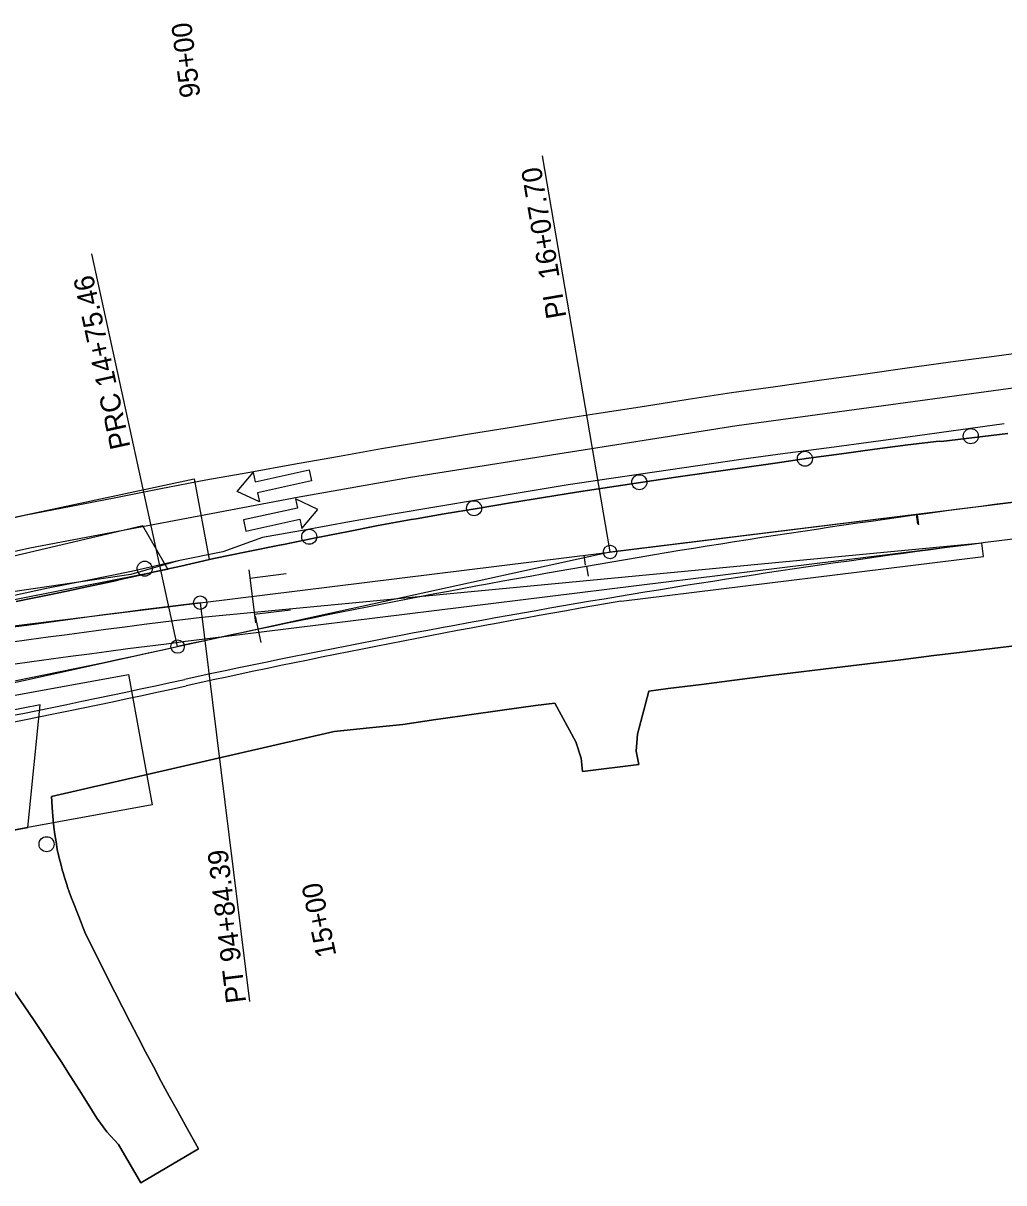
# Model space of a CAD drawing. Extents: x 1568809 to 1572786, y 728326 to 734907.
# Drawn here: x 1569721.8 to 1570014.8, y 731945.8 to 732292 of the extents above; entities that cross this region are included whole.
import ezdxf

# ---------------------------------------------------------------- set-up
doc = ezdxf.new("R2010")
doc.units = 0
for name, color, linetype in [('R_Horz Alg', 7, 'Continuous'), ('R_Horz Alg Annot', 7, 'Continuous'), ('R_MOT', 7, 'Continuous'), ('R_No Plot', 7, 'Continuous'), ('R_Proposed Const Limits_Fill', 7, 'Continuous'), ('R_Striping', 7, 'Continuous')]:
    doc.layers.add(name, color=color, linetype=linetype)

msp = doc.modelspace()

# ---------------------------------------------------------------- linework, layer by layer
at = {"layer": 'R_Horz Alg'}
msp.add_line((1569774.69, 732119.01), (1571082.41, 732280.73), dxfattribs=at)
for centre, radius, start, end in [((1570379.97, 729307.25), 2864.79, 97.05, 102.33591), ((1570243.51, 728328.17), 3819.72, 97.05, 102.61775), ((1569155.89, 734904.54), 2864.79, 276.60226, 282.33591)]:
    msp.add_arc(centre, radius, start, end, dxfattribs=at)
at = {"layer": 'R_Horz Alg Annot'}
for p, q in [((1569897.12, 732134.15), (1570028.36, 732150.38)), ((1569767.93, 732105.9), (1569897.12, 732134.15)), ((1569590.36, 732096.21), (1569774.69, 732119.01)), ((1569627.78, 732075.25), (1569767.93, 732105.9))]:
    msp.add_line(p, q, dxfattribs=at)
for points in [[(1569897.12, 732134.15), (1569876.92, 732252.44)], [(1569767.93, 732105.9), (1569742.3, 732223.13)], [(1569989.03, 732142.49), (1569988.67, 732145.47)], [(1569989.36, 732142.25), (1569988.95, 732145.23)], [(1569889.79, 732130.22), (1569889.42, 732133.2)], [(1569890.65, 732126.9), (1569890.14, 732129.85)], [(1569789.69, 732124.89), (1569790.67, 732116.95)], [(1569774.69, 732119.01), (1569789.42, 731999.91)], [(1569791.11, 732114.95), (1569792.75, 732107.12)]]:
    msp.add_lwpolyline(points, dxfattribs=at)
for centre in [(1569897.12, 732134.15), (1569774.69, 732119.01), (1569767.93, 732105.9)]:
    msp.add_circle(centre, 2, dxfattribs=at)
at = {"layer": 'R_MOT'}
for p, q in [((1569789.2, 732128.86), (1569791.16, 732112.98)), ((1569800.36, 732127.58), (1569789.52, 732126.24)), ((1569801.69, 732116.81), (1569790.85, 732115.47))]:
    msp.add_line(p, q, dxfattribs=at)
for points in [[(1569792.37, 732149.09), (1569785.71, 732152.25), (1569790.46, 732157.88), (1569791.06, 732155.14), (1569807.23, 732158.65), (1569807.95, 732155.35), (1569791.78, 732151.84)], [(1569805.05, 732141.18), (1569809.81, 732146.82), (1569803.14, 732149.97), (1569803.74, 732147.22), (1569787.57, 732143.71), (1569788.28, 732140.41), (1569804.46, 732143.93)]]:
    msp.add_lwpolyline(points, close=True, dxfattribs=at)
for centre in [(1570004.89, 732168.73), (1569955.34, 732161.99), (1569905.86, 732154.98), (1569856.5, 732147.21), (1569807.26, 732138.7), (1569758.1, 732129.16), (1569728.78, 732046.9)]:
    msp.add_circle(centre, 2.25, dxfattribs=at)
at = {"layer": 'R_No Plot'}
for p, q in [((1569599.2, 732118.84), (1569772.9, 732155.99)), ((1569772.9, 732155.99), (1569777.36, 732131.86)), ((1570008.21, 732136.8), (1569775.13, 732114.63)), ((1570008.21, 732136.8), (1569776.04, 732108.09)), ((1570008.7, 732132.83), (1570008.21, 732136.8)), ((1570008.7, 732132.83), (1570008.21, 732136.8)), ((1569900.4, 732119.44), (1570008.7, 732132.83)), ((1569900.4, 732119.44), (1570008.7, 732132.83)), ((1569814.7, 732080.55), (1569730.27, 732061.11)), ((1569730.27, 732061.11), (1569814.7, 732080.55)), ((1569774.18, 731955.95), (1569756.95, 731945.81)), ((1569756.95, 731945.81), (1569774.18, 731955.95))]:
    msp.add_line(p, q, dxfattribs=at)
for points in [[(1570014.9, 732172.44), (1570001.94, 732170.63), (1569988.99, 732168.82), (1569975.8, 732167.05), (1569962.62, 732165.29), (1569949.43, 732163.52), (1569936.25, 732161.75), (1569923.33, 732159.85), (1569910.41, 732157.95), (1569897.49, 732156.06), (1569884.56, 732154.16), (1569871.51, 732151.99), (1569858.45, 732149.82), (1569845.39, 732147.64), (1569832.33, 732145.47), (1569819.33, 732143.14), (1569806.33, 732140.81), (1569793.33, 732138.48), (1569781.46, 732134.16), (1569768.14, 732131.46), (1569753.99, 732127.44), (1569718.69, 732122.21), (1569603.22, 732101.96)], [(1570014.9, 732172.44), (1570001.94, 732170.63), (1569988.99, 732168.82), (1569975.8, 732167.05), (1569962.62, 732165.29), (1569949.43, 732163.52), (1569936.25, 732161.75), (1569923.33, 732159.85), (1569910.41, 732157.95), (1569897.49, 732156.06), (1569884.56, 732154.16), (1569871.51, 732151.99), (1569858.45, 732149.82), (1569845.39, 732147.64), (1569832.33, 732145.47), (1569819.33, 732143.14), (1569806.33, 732140.81), (1569793.33, 732138.48), (1569781.46, 732134.16), (1569768.14, 732131.46), (1569754.19, 732128.31), (1569740.87, 732125.61), (1569728.75, 732123.25), (1569716, 732120.44)], [(1569777.36, 732131.86), (1569778.71, 732132.16), (1569788.54, 732134.2), (1569798.36, 732136.19), (1569799.52, 732136.43), (1569808.2, 732138.16), (1569816.86, 732139.87), (1569818.03, 732140.1), (1569827.87, 732142.02), (1569837.73, 732143.82), (1569839.2, 732144.08), (1569847.59, 732145.5), (1569857.46, 732147.17), (1569867.34, 732148.82), (1569877.21, 732150.43), (1569887.09, 732152.02), (1569896.98, 732153.53), (1569906.88, 732155), (1569916.77, 732156.47), (1569926.67, 732157.89), (1569936.57, 732159.31), (1569946.48, 732160.7), (1569956.38, 732162.11), (1569966.29, 732163.45), (1569976.2, 732164.81), (1569986.11, 732166.13), (1569995.44, 732167.22), (1569996.06, 732167.15), (1570005.99, 732168.34), (1570015.92, 732169.51)], [(1570015.92, 732169.51), (1570005.99, 732168.34), (1569996.06, 732167.15), (1569995.44, 732167.22), (1569986.11, 732166.13), (1569976.2, 732164.81), (1569966.29, 732163.45), (1569956.38, 732162.11), (1569946.48, 732160.7), (1569936.57, 732159.31), (1569926.67, 732157.89), (1569916.77, 732156.47), (1569906.88, 732155), (1569896.98, 732153.53), (1569887.09, 732152.02), (1569877.21, 732150.43), (1569867.34, 732148.82), (1569857.46, 732147.17), (1569847.59, 732145.5), (1569839.2, 732144.08), (1569837.73, 732143.82), (1569827.87, 732142.02), (1569818.03, 732140.1), (1569816.86, 732139.87), (1569808.2, 732138.16), (1569799.52, 732136.43), (1569798.36, 732136.19), (1569788.54, 732134.2), (1569778.72, 732132.16)], [(1569778.72, 732132.16), (1569773.22, 732130.93), (1569768.89, 732129.95), (1569761.05, 732128.18), (1569759.07, 732127.73), (1569751.2, 732125.99), (1569749.24, 732125.55), (1569748.89, 732125.48), (1569739.4, 732123.44), (1569736.73, 732122.87), (1569729.57, 732121.37), (1569724.56, 732120.33), (1569719.73, 732119.38)], [(1570023.67, 732106.82), (1570013.75, 732105.61), (1570003.82, 732104.42), (1570003.21, 732104.35), (1569993.89, 732103.2), (1569983.97, 732101.96), (1569974.05, 732100.71), (1569964.12, 732099.54), (1569954.19, 732098.34), (1569944.26, 732097.13), (1569934.34, 732095.89), (1569924.42, 732094.62), (1569914.5, 732093.37), (1569908.66, 732092.64), (1569905.32, 732079.74), (1569904.97, 732074.66), (1569905.74, 732070.73), (1569888.89, 732068.64), (1569888.52, 732072.63), (1569886.94, 732077.47), (1569880.6, 732089.04), (1569874.82, 732088.29), (1569864.91, 732086.95), (1569855.01, 732085.54), (1569846.59, 732084.33), (1569845.11, 732084.12), (1569835.21, 732082.66), (1569825.26, 732081.67), (1569814.7, 732080.55)], [(1569814.7, 732080.55), (1569825.26, 732081.67), (1569835.21, 732082.66), (1569845.11, 732084.12), (1569846.59, 732084.33), (1569855.01, 732085.54), (1569864.91, 732086.95), (1569874.82, 732088.29), (1569880.6, 732089.04), (1569886.94, 732077.47), (1569888.52, 732072.63), (1569888.89, 732068.64), (1569905.74, 732070.73), (1569904.97, 732074.66), (1569905.32, 732079.74), (1569908.66, 732092.64), (1569914.5, 732093.37), (1569924.42, 732094.62), (1569934.34, 732095.89), (1569944.26, 732097.13), (1569954.19, 732098.34), (1569964.12, 732099.54), (1569974.05, 732100.71), (1569983.97, 732101.96), (1569993.89, 732103.2), (1570003.21, 732104.35), (1570003.82, 732104.42), (1570013.75, 732105.61), (1570023.67, 732106.82)], [(1569730.27, 732061.11), (1569730.52, 732056.51), (1569730.53, 732056.42), (1569730.73, 732054.21), (1569730.98, 732052.04), (1569730.98, 732052), (1569731.29, 732049.8), (1569731.62, 732047.59), (1569731.62, 732047.58), (1569731.99, 732045.37), (1569732.47, 732043.19), (1569732.48, 732043.12), (1569733, 732041.01), (1569733.58, 732038.84), (1569733.61, 732038.72), (1569734.21, 732036.68), (1569734.9, 732034.53), (1569734.95, 732034.37), (1569735.63, 732032.39), (1569736.42, 732030.27), (1569736.51, 732030.05), (1569738.39, 732025.36), (1569740.25, 732020.66), (1569742.42, 732016.15), (1569744.67, 732011.67), (1569746.9, 732007.18), (1569749.16, 732002.72), (1569751.46, 731998.27), (1569753.74, 731993.81), (1569756.04, 731989.37), (1569758.36, 731984.93), (1569760.7, 731980.51), (1569763.06, 731976.1), (1569765.44, 731971.71), (1569767.86, 731967.33), (1569770.26, 731962.94), (1569774.18, 731955.95)], [(1569774.18, 731955.95), (1569770.26, 731962.94), (1569767.86, 731967.33), (1569765.44, 731971.71), (1569763.06, 731976.1), (1569760.7, 731980.51), (1569758.36, 731984.93), (1569756.04, 731989.37), (1569753.74, 731993.81), (1569751.46, 731998.27), (1569749.16, 732002.72), (1569746.9, 732007.18), (1569744.67, 732011.67), (1569742.42, 732016.15), (1569740.25, 732020.66), (1569738.39, 732025.36), (1569736.51, 732030.05), (1569736.42, 732030.27), (1569735.63, 732032.39), (1569734.95, 732034.37), (1569734.9, 732034.53), (1569734.21, 732036.68), (1569733.61, 732038.72), (1569733.58, 732038.84), (1569733, 732041.01), (1569732.48, 732043.12), (1569732.47, 732043.19), (1569731.99, 732045.37), (1569731.62, 732047.58), (1569731.62, 732047.59), (1569731.29, 732049.8), (1569730.98, 732052), (1569730.98, 732052.04), (1569730.73, 732054.21), (1569730.53, 732056.42), (1569730.52, 732056.51), (1569730.27, 732061.11)], [(1569756.95, 731945.81), (1569750.25, 731957.21), (1569746.79, 731960.99), (1569743.85, 731965.06), (1569741.2, 731969.31), (1569738.56, 731973.56), (1569735.86, 731977.78), (1569733.14, 731981.98), (1569730.4, 731986.17), (1569727.65, 731990.36), (1569724.87, 731994.53), (1569722.06, 731998.68), (1569719.24, 732002.82)], [(1569719.24, 732002.82), (1569722.06, 731998.68), (1569724.87, 731994.53), (1569727.65, 731990.36), (1569730.4, 731986.17), (1569733.14, 731981.98), (1569735.86, 731977.78), (1569738.56, 731973.56), (1569741.2, 731969.31), (1569743.85, 731965.06), (1569746.79, 731960.99), (1569750.25, 731957.21), (1569756.95, 731945.81)]]:
    msp.add_lwpolyline(points, dxfattribs=at)
for points in [[(1569601.29, 732105.28), (1569603.2, 732097.08), (1569764.97, 732129.06), (1569757.55, 732142)], [(1569361.7, 732026.33), (1569753.23, 732097.58), (1569760.32, 732058.65), (1569368.79, 731987.39)], [(1569686.14, 732080.55), (1569700.8, 732047.66), (1569723.22, 732051.87), (1569726.84, 732088.5)]]:
    msp.add_lwpolyline(points, close=True, dxfattribs=at)
for centre, radius, start, end in [((1570379.97, 729307.25), 2852.79, 99.67786, 102.33591), ((1570379.97, 729307.25), 2852.79, 99.67786, 102.33591), ((1570242.6, 728334.71), 3808.72, 97.05, 102.61775), ((1570243.51, 728328.17), 3808.72, 97.05, 102.61775), ((1569155.89, 734904.54), 2876.79, 276.60226, 282.33591), ((1569155.89, 734904.54), 2876.79, 276.60226, 282.33592)]:
    msp.add_arc(centre, radius, start, end, dxfattribs=at)
at = {"layer": 'R_Proposed Const Limits_Fill'}
msp.add_lwpolyline([(1569719.73, 732119.38), (1569724.56, 732120.33), (1569729.57, 732121.37), (1569736.73, 732122.87), (1569739.4, 732123.44), (1569748.89, 732125.48), (1569749.24, 732125.55), (1569751.2, 732125.99), (1569759.07, 732127.73), (1569761.05, 732128.18), (1569768.89, 732129.95), (1569773.22, 732130.93), (1569778.71, 732132.16), (1569788.54, 732134.2), (1569798.36, 732136.19), (1569799.52, 732136.43), (1569808.2, 732138.16), (1569816.86, 732139.87), (1569818.03, 732140.1), (1569827.87, 732142.02), (1569837.73, 732143.82), (1569839.2, 732144.08), (1569847.59, 732145.5), (1569857.46, 732147.17), (1569867.34, 732148.82), (1569877.21, 732150.43), (1569887.09, 732152.02), (1569896.98, 732153.53), (1569906.88, 732155), (1569916.77, 732156.47), (1569926.67, 732157.89), (1569936.57, 732159.31), (1569946.48, 732160.7), (1569956.38, 732162.11), (1569966.29, 732163.45), (1569976.2, 732164.81), (1569986.11, 732166.13), (1569995.44, 732167.21), (1569996.06, 732167.15), (1570005.99, 732168.34), (1570015.92, 732169.51)], dxfattribs=at)
at = {"layer": 'R_Striping'}
for points in [[(1569091.81, 731985.64), (1569147.99, 731999.1), (1569330.25, 732041.98), (1569622.48, 732112.98), (1569698.68, 732129.84), (1569723.78, 732135.38), (1569804.21, 732150.59), (1569837.55, 732156.52), (1569935.04, 732171.96), (1570097.77, 732194.1), (1570522.6, 732247.41)], [(1569709.87, 732142.41), (1569722.68, 732145.21), (1569736.1, 732147.83), (1569749.51, 732150.45), (1569762.93, 732153.07), (1569776.35, 732155.68), (1569789.47, 732158.02), (1569802.59, 732160.35), (1569815.71, 732162.68), (1569828.83, 732165.01), (1569841.96, 732167.19), (1569855.1, 732169.38), (1569868.24, 732171.56), (1569881.38, 732173.75), (1569894.39, 732175.74), (1569907.4, 732177.73), (1569920.41, 732179.73), (1569933.42, 732181.72), (1569946.52, 732183.57), (1569959.63, 732185.42), (1569972.73, 732187.27), (1569985.84, 732189.13), (1569998.86, 732190.89), (1570011.89, 732192.66), (1570024.92, 732194.42)]]:
    msp.add_lwpolyline(points, dxfattribs=at)
for centre, radius, start, end in [((1570369.29, 729305.42), 2854.31, 96.83257, 102.11849), ((1570379.97, 729307.25), 2852.79, 99.67786, 102.33591), ((1569155.89, 734904.54), 2874.79, 276.60226, 282.33591), ((1569155.89, 734904.54), 2876.79, 276.60226, 282.33591)]:
    msp.add_arc(centre, radius, start, end, dxfattribs=at)

# ---------------------------------------------------------------- texts
at = {"layer": 'R_Horz Alg Annot'}
for s, rotation, p in [('95+00', 97.05, (1569774.74, 732270.16)), ('PI  16+07.70', 99.693, (1569884.12, 732204.35)), ('PRC 14+75.46', 102.3359, (1569753.86, 732165.54)), ('PT 94+84.39', 97.05, (1569788.43, 731999.79)), ('15+00', 101.845, (1569815.39, 732013.78))]:
    msp.add_text(s, height=6, rotation=rotation, dxfattribs=at).set_placement(p)

doc.saveas('drawing.dxf')
